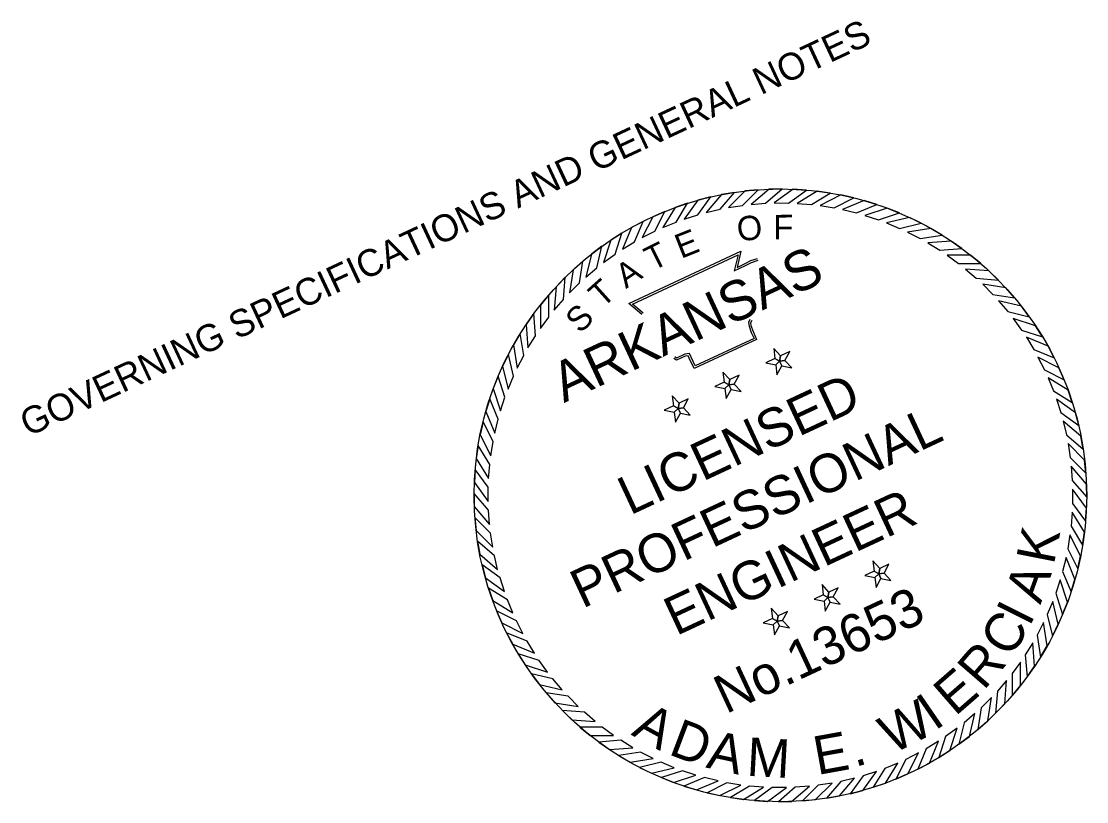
# Model space of a CAD drawing. Extents: x 756526 to 763735, y 1656374 to 1661090.
# Drawn here: x 762619.5 to 763036.9, y 1660474.4 to 1660780.1 of the extents above; entities that cross this region are included whole.
import ezdxf

# ---------------------------------------------------------------- set-up
doc = ezdxf.new("R2010")
doc.units = 0
for name, color, linetype in [('1', 7, 'Continuous'), ('G-ANNO-STMP', 7, 'Continuous'), ('G-No Plot-Stamp-1', 7, 'Continuous')]:
    doc.layers.add(name, color=color, linetype=linetype)

msp = doc.modelspace()

# ---------------------------------------------------------------- linework, layer by layer
at = {"layer": 'G-ANNO-STMP'}
for points in [[(762898.89, 1660713.06), (762893.8, 1660712.17), (762887.83, 1660705.18), (762893.25, 1660706.46)], [(762908.25, 1660714.1), (762903.11, 1660713.62), (762896.61, 1660707.12), (762902.12, 1660707.97)], [(762917.67, 1660714.41), (762912.51, 1660714.34), (762905.51, 1660708.36), (762911.07, 1660708.78)], [(762927.08, 1660713.98), (762921.93, 1660714.31), (762914.49, 1660708.91), (762920.06, 1660708.89)], [(762936.43, 1660712.82), (762931.32, 1660713.55), (762923.48, 1660708.74), (762929.04, 1660708.29)], [(762880.55, 1660708.78), (762875.66, 1660707.11), (762870.86, 1660699.26), (762876.02, 1660701.38)], [(762889.63, 1660711.28), (762884.63, 1660709.99), (762879.23, 1660702.55), (762884.53, 1660704.26)], [(762945.66, 1660710.92), (762940.63, 1660712.05), (762932.43, 1660707.87), (762937.93, 1660706.98)], [(762954.71, 1660708.31), (762949.78, 1660709.83), (762941.28, 1660706.31), (762946.7, 1660704.99)], [(762871.69, 1660705.57), (762866.95, 1660703.52), (762862.77, 1660695.33), (762867.75, 1660697.84)], [(762963.53, 1660704.99), (762958.74, 1660706.89), (762949.99, 1660704.05), (762955.29, 1660702.31)], [(762863.1, 1660701.68), (762858.54, 1660699.27), (762855.02, 1660690.77), (762859.78, 1660693.67)], [(762972.07, 1660700.99), (762967.43, 1660703.26), (762958.49, 1660701.12), (762963.63, 1660698.97)], [(762854.85, 1660697.13), (762850.49, 1660694.36), (762847.65, 1660685.62), (762852.17, 1660688.88)], [(762980.26, 1660696.33), (762975.82, 1660698.96), (762966.73, 1660697.52), (762971.69, 1660694.98)], [(762988.06, 1660691.05), (762983.84, 1660694.02), (762974.67, 1660693.3), (762979.41, 1660690.37)], [(762846.99, 1660691.94), (762842.86, 1660688.84), (762840.71, 1660679.9), (762844.96, 1660683.51)], [(762995.42, 1660685.17), (762991.45, 1660688.46), (762982.25, 1660688.46), (762986.75, 1660685.17)], [(762839.55, 1660686.15), (762835.68, 1660682.74), (762834.24, 1660673.66), (762838.19, 1660677.59)], [(762832.59, 1660679.8), (762829, 1660676.1), (762828.27, 1660666.93), (762831.91, 1660671.16)], [(763002.3, 1660678.73), (762998.6, 1660682.32), (762989.43, 1660683.04), (762993.66, 1660679.41)], [(763008.65, 1660671.77), (763005.24, 1660675.64), (762996.16, 1660677.08), (763000.09, 1660673.13)], [(762826.15, 1660672.92), (762822.86, 1660668.95), (762822.86, 1660659.75), (762826.15, 1660664.25)], [(763014.44, 1660664.33), (763011.34, 1660668.46), (763002.4, 1660670.61), (763006.01, 1660666.36)], [(762820.27, 1660665.56), (762817.3, 1660661.34), (762818.02, 1660652.17), (762820.95, 1660656.91)], [(763019.63, 1660656.46), (763016.86, 1660660.82), (763008.12, 1660663.67), (763011.38, 1660659.14)], [(762814.98, 1660657.76), (762812.35, 1660653.32), (762813.79, 1660644.23), (762816.34, 1660649.19)], [(763024.18, 1660648.21), (763021.77, 1660652.78), (763013.27, 1660656.3), (763016.17, 1660651.53)], [(762916.6, 1660646.99), (762917, 1660649.05), (762914.28, 1660651.97), (762914.77, 1660648.01)], [(762916.6, 1660646.99), (762918.68, 1660647.25), (762920.61, 1660650.73), (762917, 1660649.05)], [(762810.33, 1660649.57), (762808.05, 1660644.93), (762810.2, 1660635.99), (762812.35, 1660641.13)], [(762916.6, 1660646.99), (762914.77, 1660648.01), (762911.16, 1660646.32), (762915.07, 1660645.56)], [(762916.6, 1660646.99), (762915.07, 1660645.56), (762915.55, 1660641.61), (762917.49, 1660645.09)], [(762916.6, 1660646.99), (762917.49, 1660645.09), (762921.4, 1660644.33), (762918.68, 1660647.25)], [(763028.07, 1660639.63), (763026.02, 1660644.37), (763017.83, 1660648.55), (763020.34, 1660643.57)], [(762896.71, 1660637.72), (762897.11, 1660639.78), (762894.39, 1660642.69), (762894.88, 1660638.74)], [(762806.33, 1660641.03), (762804.43, 1660636.24), (762807.27, 1660627.49), (762809.01, 1660632.79)], [(762896.71, 1660637.72), (762894.88, 1660638.74), (762891.27, 1660637.05), (762895.18, 1660636.29)], [(762896.71, 1660637.72), (762898.79, 1660637.97), (762900.73, 1660641.46), (762897.11, 1660639.78)], [(762896.71, 1660637.72), (762897.6, 1660635.82), (762901.51, 1660635.06), (762898.79, 1660637.97)], [(763031.27, 1660630.77), (763029.61, 1660635.65), (763021.76, 1660640.46), (763023.88, 1660635.3)], [(762896.71, 1660637.72), (762895.18, 1660636.29), (762895.67, 1660632.33), (762897.6, 1660635.82)], [(762803.01, 1660632.21), (762801.49, 1660627.28), (762805.01, 1660618.78), (762806.33, 1660624.2)], [(762876.82, 1660628.45), (762874.99, 1660629.46), (762871.38, 1660627.78), (762875.29, 1660627.02)], [(762876.82, 1660628.45), (762877.22, 1660630.5), (762874.51, 1660633.42), (762874.99, 1660629.46)], [(762876.82, 1660628.45), (762878.9, 1660628.7), (762880.84, 1660632.19), (762877.22, 1660630.5)], [(763033.78, 1660621.69), (763032.49, 1660626.69), (763025.05, 1660632.09), (763026.76, 1660626.78)], [(762876.82, 1660628.45), (762875.29, 1660627.02), (762875.78, 1660623.06), (762877.71, 1660626.55)], [(762876.82, 1660628.45), (762877.71, 1660626.55), (762881.62, 1660625.79), (762878.9, 1660628.7)], [(762800.4, 1660623.16), (762799.27, 1660618.13), (762803.44, 1660609.93), (762804.33, 1660615.43)], [(763035.56, 1660612.43), (763034.67, 1660617.52), (763027.68, 1660623.49), (763028.96, 1660618.07)], [(762798.5, 1660613.93), (762797.77, 1660608.82), (762802.58, 1660600.98), (762803.03, 1660606.54)], [(763036.6, 1660603.07), (763036.12, 1660608.21), (763029.62, 1660614.71), (763030.47, 1660609.2)], [(762797.33, 1660604.58), (762797.01, 1660599.43), (762802.41, 1660591.99), (762802.43, 1660597.56)], [(763036.91, 1660593.65), (763036.84, 1660598.81), (763030.86, 1660605.8), (763031.28, 1660600.25)], [(763036.48, 1660584.24), (763036.81, 1660589.39), (763031.4, 1660596.83), (763031.39, 1660591.25)], [(762796.9, 1660595.17), (762796.98, 1660590.01), (762802.96, 1660583.01), (762802.54, 1660588.57)], [(763035.32, 1660574.89), (763036.05, 1660580), (763031.24, 1660587.84), (763030.79, 1660582.28)], [(762797.21, 1660585.75), (762797.7, 1660580.61), (762804.2, 1660574.11), (762803.35, 1660579.62)], [(762798.26, 1660576.39), (762799.15, 1660571.3), (762806.14, 1660565.33), (762804.86, 1660570.75)], [(763033.42, 1660565.66), (763034.55, 1660570.69), (763030.37, 1660578.89), (763029.48, 1660573.38)], [(762800.04, 1660567.13), (762801.32, 1660562.13), (762808.76, 1660556.73), (762807.06, 1660562.03)], [(762955.44, 1660563.71), (762955.84, 1660565.77), (762953.12, 1660568.68), (762953.6, 1660564.73)], [(762955.44, 1660563.71), (762957.52, 1660563.97), (762959.45, 1660567.45), (762955.84, 1660565.77)], [(763030.81, 1660556.6), (763032.33, 1660561.54), (763028.81, 1660570.03), (763027.49, 1660564.62)], [(762955.44, 1660563.71), (762953.6, 1660564.73), (762949.99, 1660563.04), (762953.9, 1660562.28)], [(762955.44, 1660563.71), (762953.9, 1660562.28), (762954.39, 1660558.33), (762956.32, 1660561.81)], [(762955.44, 1660563.71), (762956.32, 1660561.81), (762960.23, 1660561.05), (762957.52, 1660563.97)], [(762935.55, 1660554.44), (762935.95, 1660556.49), (762933.23, 1660559.41), (762933.72, 1660555.45)], [(763027.49, 1660547.78), (763029.39, 1660552.58), (763026.55, 1660561.33), (763024.81, 1660556.03)], [(762802.54, 1660558.05), (762804.21, 1660553.16), (762812.05, 1660548.36), (762809.94, 1660553.52)], [(762935.55, 1660554.44), (762933.72, 1660555.45), (762930.1, 1660553.77), (762934.02, 1660553.01)], [(762935.55, 1660554.44), (762934.02, 1660553.01), (762934.5, 1660549.05), (762936.43, 1660552.54)], [(762935.55, 1660554.44), (762937.63, 1660554.69), (762939.56, 1660558.18), (762935.95, 1660556.49)], [(762935.55, 1660554.44), (762936.43, 1660552.54), (762940.35, 1660551.78), (762937.63, 1660554.69)], [(762915.66, 1660545.16), (762916.06, 1660547.22), (762913.34, 1660550.14), (762913.83, 1660546.18)], [(763023.49, 1660539.25), (763025.76, 1660543.89), (763023.62, 1660552.83), (763021.47, 1660547.68)], [(762805.75, 1660549.19), (762807.8, 1660544.45), (762815.99, 1660540.27), (762813.48, 1660545.25)], [(762915.66, 1660545.16), (762913.83, 1660546.18), (762910.21, 1660544.49), (762914.13, 1660543.73)], [(762915.66, 1660545.16), (762917.74, 1660545.42), (762919.67, 1660548.9), (762916.06, 1660547.22)], [(762915.66, 1660545.16), (762914.13, 1660543.73), (762914.61, 1660539.78), (762916.55, 1660543.26)], [(762915.66, 1660545.16), (762916.55, 1660543.26), (762920.46, 1660542.5), (762917.74, 1660545.42)], [(763018.83, 1660531.06), (763021.46, 1660535.5), (763020.02, 1660544.59), (763017.48, 1660539.63)], [(762809.64, 1660540.6), (762812.05, 1660536.04), (762820.55, 1660532.52), (762817.65, 1660537.28)], [(763013.55, 1660523.26), (763016.52, 1660527.48), (763015.8, 1660536.65), (763012.87, 1660531.9)], [(762814.19, 1660532.35), (762816.95, 1660527.99), (762825.7, 1660525.15), (762822.44, 1660529.67)], [(763007.67, 1660515.9), (763010.96, 1660519.87), (763010.96, 1660529.07), (763007.67, 1660524.57)], [(762819.38, 1660524.49), (762822.47, 1660520.36), (762831.42, 1660518.21), (762827.81, 1660522.46)], [(763001.23, 1660509.02), (763004.82, 1660512.72), (763005.54, 1660521.89), (763001.91, 1660517.66)], [(762825.16, 1660517.05), (762828.57, 1660513.18), (762837.66, 1660511.74), (762833.73, 1660515.69)], [(762994.27, 1660502.66), (762998.14, 1660506.07), (762999.58, 1660515.16), (762995.63, 1660511.23)], [(762831.52, 1660510.09), (762835.22, 1660506.5), (762844.39, 1660505.77), (762840.16, 1660509.41)], [(762986.83, 1660496.88), (762990.96, 1660499.97), (762993.11, 1660508.92), (762988.86, 1660505.31)], [(762838.39, 1660503.65), (762842.37, 1660500.36), (762851.57, 1660500.36), (762847.07, 1660503.65)], [(762978.96, 1660491.69), (762983.32, 1660494.45), (762986.17, 1660503.2), (762981.64, 1660499.94)], [(762845.76, 1660497.77), (762849.98, 1660494.8), (762859.15, 1660495.52), (762854.4, 1660498.45)], [(762970.71, 1660487.14), (762975.28, 1660489.55), (762978.8, 1660498.05), (762974.03, 1660495.15)], [(762853.56, 1660492.48), (762858, 1660489.85), (762867.08, 1660491.29), (762862.13, 1660493.84)], [(762962.13, 1660483.25), (762966.87, 1660485.3), (762971.04, 1660493.49), (762966.07, 1660490.98)], [(762861.75, 1660487.83), (762866.38, 1660485.56), (762875.33, 1660487.7), (762870.18, 1660489.85)], [(762953.27, 1660480.04), (762958.15, 1660481.71), (762962.96, 1660489.55), (762957.8, 1660487.44)], [(762870.28, 1660483.83), (762875.08, 1660481.93), (762883.83, 1660484.77), (762878.53, 1660486.51)], [(762879.1, 1660480.51), (762884.04, 1660478.99), (762892.53, 1660482.51), (762887.12, 1660483.83)], [(762934.93, 1660475.76), (762940.02, 1660476.65), (762945.99, 1660483.64), (762940.56, 1660482.36)], [(762944.19, 1660477.54), (762949.18, 1660478.82), (762954.59, 1660486.26), (762949.28, 1660484.56)], [(762888.16, 1660477.9), (762893.19, 1660476.77), (762901.39, 1660480.94), (762895.88, 1660481.83)], [(762897.39, 1660476), (762902.5, 1660475.27), (762910.34, 1660480.08), (762904.78, 1660480.53)], [(762906.74, 1660474.83), (762911.89, 1660474.51), (762919.33, 1660479.91), (762913.75, 1660479.93)], [(762916.15, 1660474.4), (762921.31, 1660474.48), (762928.3, 1660480.46), (762922.74, 1660480.04)], [(762925.57, 1660474.71), (762930.71, 1660475.2), (762937.21, 1660481.7), (762931.7, 1660480.85)]]:
    msp.add_lwpolyline(points, close=True, dxfattribs=at)
for points in [[(762862.67, 1660665.22), (762857.58, 1660669.53), (762901.44, 1660690.01), (762899.92, 1660683.7), (762902.88, 1660685.13), (762905.36, 1660686.32), (762907.97, 1660687.21)], [(762863.17, 1660665.81), (762858.99, 1660669.34), (762900.32, 1660688.65), (762898.8, 1660682.31), (762903.21, 1660684.44), (762905.65, 1660685.61), (762908.22, 1660686.48)], [(762905.67, 1660662.89), (762905.2, 1660661.93), (762905.38, 1660660.91), (762906.19, 1660658.52), (762907.61, 1660655.48), (762883.12, 1660644.06), (762881.21, 1660648.16), (762880.78, 1660649.07), (762879.65, 1660648.91), (762876.17, 1660647.28), (762875.11, 1660647.94)], [(762904.98, 1660663.22), (762904.41, 1660662.04), (762904.63, 1660660.72), (762905.48, 1660658.23), (762906.59, 1660655.85), (762883.49, 1660645.08), (762881.9, 1660648.48), (762881.24, 1660649.91), (762879.43, 1660649.65), (762876.22, 1660648.15), (762875.51, 1660648.59)]]:
    msp.add_lwpolyline(points, dxfattribs=at)
at = {"layer": 'G-No Plot-Stamp-1'}
msp.add_circle((762916.91, 1660594.4), 120, dxfattribs=at)

# ---------------------------------------------------------------- texts
at = {"layer": '1'}
msp.add_text('GOVERNING SPECIFICATIONS AND GENERAL NOTES', height=10.5516, rotation=25, dxfattribs=at).set_placement((762622.21, 1660617.22))
at = {"layer": 'G-ANNO-STMP'}
for s, height, rotation, p in [('O', 9.55, 6.2218, (762900.38, 1660693.83)), ('F', 9.55, 0.3628, (762914.17, 1660694.7)), ('E', 9.55, 21.672, (762877.98, 1660686.99)), ('T', 9.55, 26.4789, (762866.78, 1660682.09)), ('ARKANSAS', 15.584, 25, (762832.11, 1660630.51)), ('A', 9.55, 33.6788, (762856.41, 1660675.16)), ('T', 9.55, 41.9015, (762847.18, 1660667.52)), ('S', 9.55, 44.7726, (762838.48, 1660657.45)), ('LICENSED', 15.087, 25, (762858, 1660586.45)), ('PROFESSIONAL', 15.0867, 25, (762839.36, 1660549.92)), ('ENGINEER', 15.087, 25, (762876.07, 1660539.2)), ('K', 15.09, 78.8471, (763024.03, 1660566.89)), ('A', 15.09, 70.185, (763018.78, 1660551.38)), ('No.13653', 15.027, 25, (762895.58, 1660508.62)), ('I', 15.09, 63.4057, (763014.46, 1660542.61)), ('C', 15.09, 57.1396, (763006.97, 1660530.33)), ('R', 15.09, 49.1616, (762996.56, 1660517.7)), ('E', 15.09, 41.0125, (762985.38, 1660507.62)), ('W', 15.09, 27.1127, (762960.76, 1660492.81)), ('I', 15.09, 34.5753, (762977.4, 1660501.99)), ('A', 15.09, 330.982, (762858.14, 1660500.73)), ('D', 15.09, 339.3022, (762872.63, 1660493.1)), ('A', 15.09, 347.6223, (762887.43, 1660487.83)), ('E', 15.09, 10.2782, (762931.41, 1660484.82)), ('M', 15.09, 356.7969, (762903.48, 1660484.57)), ('.', 15.09, 15.8583, (762946.13, 1660487.92))]:
    msp.add_text(s, height=height, rotation=rotation, dxfattribs=at).set_placement(p)

doc.saveas('drawing.dxf')
